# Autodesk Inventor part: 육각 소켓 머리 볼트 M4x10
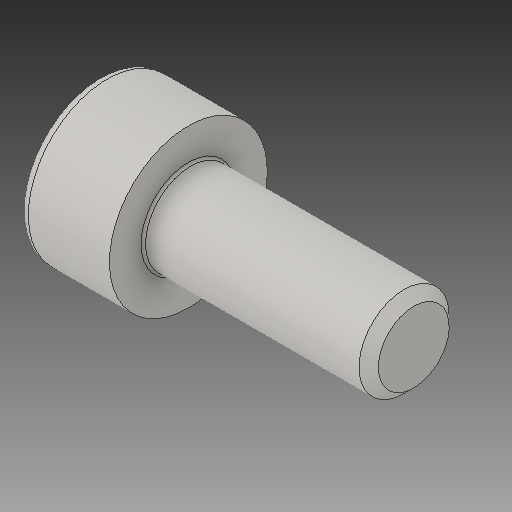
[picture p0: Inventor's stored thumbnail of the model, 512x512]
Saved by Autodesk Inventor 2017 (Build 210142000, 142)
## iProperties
Created: 2024-08
Part Number: 육각 소켓 머리 볼트 M4x10
Material: 일반
Description: 6각머리 태핑 나사
Document SubType Name: Modeling
Designer: MRC
Density: 1 g/cm^3
Appearance: 기본값
Author: jhkim
Sending System: Autodesk Inventor 2025
Preprocessor: ST-DEVELOPER v20
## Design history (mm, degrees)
feature "Solid1"
node "솔리드1"
